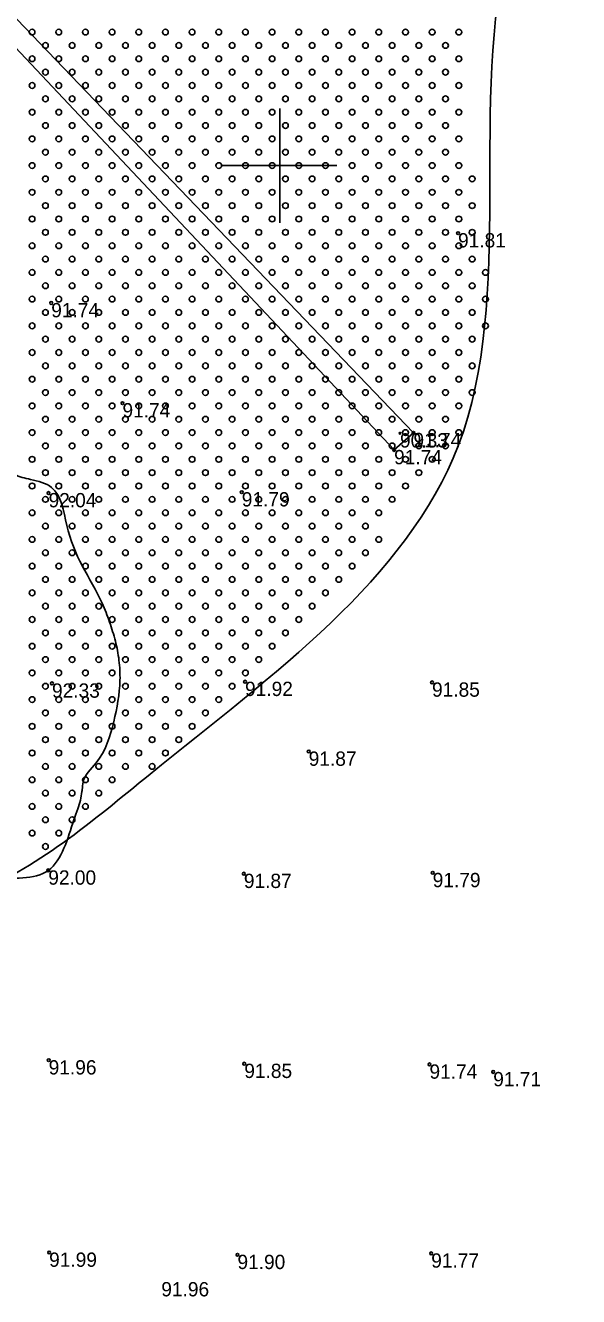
# Model space of a CAD drawing. Extents: x 316000 to 728450, y 314368 to 726000.
# Drawn here: x 725933.2 to 726078.4, y 314703.5 to 315036.8 of the extents above; entities that cross this region are included whole.
import ezdxf

# ---------------------------------------------------------------- set-up
doc = ezdxf.new("R2010")
doc.units = 0
for name, color, linetype in [('GEOD_ELEM_####_####_#', 7, 'Continuous'), ('HIDG_ELEM_####_####_#', 7, 'Continuous'), ('HIDG_GRAV_####_####_#', 7, 'Continuous'), ('RELJ_AATZ_####_TKST_#', 7, 'Continuous'), ('RELJ_ELEM_####_####_#', 7, 'Continuous'), ('RELJ_HORZ_RESN_####_#', 7, 'Continuous'), ('TERT_ELEM_####_####_#', 7, 'Continuous'), ('TERT_KONT_####_####_#', 7, 'Continuous')]:
    doc.layers.add(name, color=color, linetype=linetype)

msp = doc.modelspace()

# ---------------------------------------------------------------- linework, layer by layer
at = {"layer": 'GEOD_ELEM_####_####_#'}
for p, q in [((726000, 315015), (726000, 315000)), ((725985, 315000), (726000, 315000)), ((726000, 315000), (726000, 314985)), ((726000, 315000), (726015, 315000))]:
    msp.add_line(p, q, dxfattribs=at)
at = {"layer": 'HIDG_ELEM_####_####_#'}
msp.add_circle((726031.57, 314929.83), 0.225, dxfattribs=at)
at = {"layer": 'HIDG_GRAV_####_####_#'}
msp.add_lwpolyline([(725550.64, 315437.37), (725654.91, 315324.09), (725793.17, 315176.93), (726030.02, 314925.45), (726035.1, 314929.94), (725796.17, 315178.83)], dxfattribs=at)
at = {"layer": 'RELJ_ELEM_####_####_#'}
for centre in [(726046.8, 314982.3), (725940.03, 314963.98), (725958.73, 314937.73), (726035.1, 314929.94), (726030.02, 314925.45), (725939.33, 314914.16), (725990.03, 314914.39), (725940.23, 314864.25), (725990.9, 314864.69), (726039.97, 314864.51), (726007.6, 314846.4), (725939.26, 314815.23), (725990.59, 314814.36), (726040.15, 314814.58), (725939.36, 314765.47), (725990.7, 314764.55), (726039.3, 314764.36), (726056.03, 314762.38), (725939.48, 314715.05), (725988.91, 314714.46), (726039.76, 314714.83)]:
    msp.add_circle(centre, 0.375, dxfattribs=at)
at = {"layer": 'RELJ_HORZ_RESN_####_#'}
msp.add_spline([(725847.58, 314913.36), (725842.82, 314903.9), (725834.89, 314893.88), (725830, 314887.5), (725824.68, 314882.5), (725823, 314880.5), (725818.46, 314873.33), (725816.42, 314861.94), (725828.62, 314847.89), (725836.39, 314833.94), (725841.85, 314827.21), (725844.92, 314823.94), (725846.54, 314822.33), (725848.21, 314820.75), (725849.87, 314819.28), (725851.54, 314817.96), (725854.93, 314815.69), (725861.88, 314812.56), (725876.18, 314810.77), (725889.21, 314809.58), (725897.6, 314810.61), (725900.35, 314811.35), (725904.45, 314811.73), (725909.6, 314811.98), (725914.71, 314812.55), (725924.78, 314813.21), (725939.26, 314815.23), (725946, 314828.5), (725947.02, 314831.36), (725947.68, 314833.6), (725948.09, 314835.89), (725948.17, 314836.43), (725948.37, 314838.35), (725951.84, 314843.45), (725956.45, 314854.2), (725958.07, 314865.07), (725957.81, 314870.33), (725957.42, 314872.87), (725956.86, 314875.34), (725955.34, 314880.33), (725953.4, 314885.29), (725948.2, 314895.01), (725944.11, 314905.69), (725940.13, 314915.61), (725934.59, 314917.71), (725930.31, 314919.02), (725927.36, 314920.28), (725925.87, 314920.52), (725924.32, 314920.84), (725921.47, 314921.64), (725910.61, 314924.89), (725899.55, 314928.31), (725893.93, 314929.77), (725888.26, 314931.21), (725887.09, 314931.52)], degree=3, dxfattribs=at)
at = {"layer": 'TERT_ELEM_####_####_#'}
for centre in [(725935, 315035), (725942, 315035), (725949, 315035), (725956, 315035), (725963, 315035), (725970, 315035), (725977, 315035), (725984, 315035), (725991, 315035), (725998, 315035), (726005, 315035), (726012, 315035), (726019, 315035), (726026, 315035), (726033, 315035), (726040, 315035), (726047, 315035), (725938.5, 315031.5), (725945.5, 315031.5), (725952.5, 315031.5), (725959.5, 315031.5), (725966.5, 315031.5), (725973.5, 315031.5), (725980.5, 315031.5), (725987.5, 315031.5), (725994.5, 315031.5), (726001.5, 315031.5), (726008.5, 315031.5), (726015.5, 315031.5), (726022.5, 315031.5), (726029.5, 315031.5), (726036.5, 315031.5), (726043.5, 315031.5), (725935, 315028), (725942, 315028), (725949, 315028), (725956, 315028), (725963, 315028), (725970, 315028), (725977, 315028), (725984, 315028), (725991, 315028), (725998, 315028), (726005, 315028), (726012, 315028), (726019, 315028), (726026, 315028), (726033, 315028), (726040, 315028), (726047, 315028), (725938.5, 315024.5), (725945.5, 315024.5), (725952.5, 315024.5), (725959.5, 315024.5), (725966.5, 315024.5), (725973.5, 315024.5), (725980.5, 315024.5), (725987.5, 315024.5), (725994.5, 315024.5), (726001.5, 315024.5), (726008.5, 315024.5), (726015.5, 315024.5), (726022.5, 315024.5), (726029.5, 315024.5), (726036.5, 315024.5), (726043.5, 315024.5), (725935, 315021), (725942, 315021), (725949, 315021), (725956, 315021), (725963, 315021), (725970, 315021), (725977, 315021), (725984, 315021), (725991, 315021), (725998, 315021), (726005, 315021), (726012, 315021), (726019, 315021), (726026, 315021), (726033, 315021), (726040, 315021), (726047, 315021), (725938.5, 315017.5), (725945.5, 315017.5), (725952.5, 315017.5), (725959.5, 315017.5), (725966.5, 315017.5), (725973.5, 315017.5), (725980.5, 315017.5), (725987.5, 315017.5), (725994.5, 315017.5), (726001.5, 315017.5), (726008.5, 315017.5), (726015.5, 315017.5), (726022.5, 315017.5), (726029.5, 315017.5), (726036.5, 315017.5), (726043.5, 315017.5), (725935, 315014), (725942, 315014), (725949, 315014), (725956, 315014), (725963, 315014), (725970, 315014), (725977, 315014), (725984, 315014), (725991, 315014), (725998, 315014), (726005, 315014), (726012, 315014), (726019, 315014), (726026, 315014), (726033, 315014), (726040, 315014), (726047, 315014), (725938.5, 315010.5), (725945.5, 315010.5), (725952.5, 315010.5), (725959.5, 315010.5), (725966.5, 315010.5), (725973.5, 315010.5), (725980.5, 315010.5), (725987.5, 315010.5), (725994.5, 315010.5), (726001.5, 315010.5), (726008.5, 315010.5), (726015.5, 315010.5), (726022.5, 315010.5), (726029.5, 315010.5), (726036.5, 315010.5), (726043.5, 315010.5), (725935, 315007), (725942, 315007), (725949, 315007), (725956, 315007), (725963, 315007), (725970, 315007), (725977, 315007), (725984, 315007), (725991, 315007), (725998, 315007), (726005, 315007), (726012, 315007), (726019, 315007), (726026, 315007), (726033, 315007), (726040, 315007), (726047, 315007), (725938.5, 315003.5), (725945.5, 315003.5), (725952.5, 315003.5), (725959.5, 315003.5), (725966.5, 315003.5), (725973.5, 315003.5), (725980.5, 315003.5), (725987.5, 315003.5), (725994.5, 315003.5), (726001.5, 315003.5), (726008.5, 315003.5), (726015.5, 315003.5), (726022.5, 315003.5), (726029.5, 315003.5), (726036.5, 315003.5), (726043.5, 315003.5), (725935, 315000), (725942, 315000), (725949, 315000), (725956, 315000), (725963, 315000), (725970, 315000), (725977, 315000), (725984, 315000), (725991, 315000), (725998, 315000), (726005, 315000), (726012, 315000), (726019, 315000), (726026, 315000), (726033, 315000), (726040, 315000), (726047, 315000), (725938.5, 314996.5), (725945.5, 314996.5), (725952.5, 314996.5), (725959.5, 314996.5), (725966.5, 314996.5), (725973.5, 314996.5), (725980.5, 314996.5), (725987.5, 314996.5), (725994.5, 314996.5), (726001.5, 314996.5), (726008.5, 314996.5), (726015.5, 314996.5), (726022.5, 314996.5), (726029.5, 314996.5), (726036.5, 314996.5), (726043.5, 314996.5), (726050.5, 314996.5), (725935, 314993), (725942, 314993), (725949, 314993), (725956, 314993), (725963, 314993), (725970, 314993), (725977, 314993), (725984, 314993), (725991, 314993), (725998, 314993), (726005, 314993), (726012, 314993), (726019, 314993), (726026, 314993), (726033, 314993), (726040, 314993), (726047, 314993), (725938.5, 314989.5), (725945.5, 314989.5), (725952.5, 314989.5), (725959.5, 314989.5), (725966.5, 314989.5), (725973.5, 314989.5), (725980.5, 314989.5), (725987.5, 314989.5), (725994.5, 314989.5), (726001.5, 314989.5), (726008.5, 314989.5), (726015.5, 314989.5), (726022.5, 314989.5), (726029.5, 314989.5), (726036.5, 314989.5), (726043.5, 314989.5), (726050.5, 314989.5), (725935, 314986), (725942, 314986), (725949, 314986), (725956, 314986), (725963, 314986), (725970, 314986), (725977, 314986), (725984, 314986), (725991, 314986), (725998, 314986), (726005, 314986), (726012, 314986), (726019, 314986), (726026, 314986), (726033, 314986), (726040, 314986), (726047, 314986), (725938.5, 314982.5), (725945.5, 314982.5), (725952.5, 314982.5), (725959.5, 314982.5), (725966.5, 314982.5), (725973.5, 314982.5), (725980.5, 314982.5), (725987.5, 314982.5), (725994.5, 314982.5), (726001.5, 314982.5), (726008.5, 314982.5), (726015.5, 314982.5), (726022.5, 314982.5), (726029.5, 314982.5), (726036.5, 314982.5), (726043.5, 314982.5), (726050.5, 314982.5), (725935, 314979), (725942, 314979), (725949, 314979), (725956, 314979), (725963, 314979), (725970, 314979), (725977, 314979), (725984, 314979), (725991, 314979), (725998, 314979), (726005, 314979), (726012, 314979), (726019, 314979), (726026, 314979), (726033, 314979), (726040, 314979), (726047, 314979), (725938.5, 314975.5), (725945.5, 314975.5), (725952.5, 314975.5), (725959.5, 314975.5), (725966.5, 314975.5), (725973.5, 314975.5), (725980.5, 314975.5), (725987.5, 314975.5), (725994.5, 314975.5), (726001.5, 314975.5), (726008.5, 314975.5), (726015.5, 314975.5), (726022.5, 314975.5), (726029.5, 314975.5), (726036.5, 314975.5), (726043.5, 314975.5), (726050.5, 314975.5), (725935, 314972), (725942, 314972), (725949, 314972), (725956, 314972), (725963, 314972), (725970, 314972), (725977, 314972), (725984, 314972), (725991, 314972), (725998, 314972), (726005, 314972), (726012, 314972), (726019, 314972), (726026, 314972), (726033, 314972), (726040, 314972), (726047, 314972), (726054, 314972), (725938.5, 314968.5), (725945.5, 314968.5), (725952.5, 314968.5), (725959.5, 314968.5), (725966.5, 314968.5), (725973.5, 314968.5), (725980.5, 314968.5), (725987.5, 314968.5), (725994.5, 314968.5), (726001.5, 314968.5), (726008.5, 314968.5), (726015.5, 314968.5), (726022.5, 314968.5), (726029.5, 314968.5), (726036.5, 314968.5), (726043.5, 314968.5), (726050.5, 314968.5), (725935, 314965), (725942, 314965), (725949, 314965), (725956, 314965), (725963, 314965), (725970, 314965), (725977, 314965), (725984, 314965), (725991, 314965), (725998, 314965), (726005, 314965), (726012, 314965), (726019, 314965), (726026, 314965), (726033, 314965), (726040, 314965), (726047, 314965), (726054, 314965), (725938.5, 314961.5), (725945.5, 314961.5), (725952.5, 314961.5), (725959.5, 314961.5), (725966.5, 314961.5), (725973.5, 314961.5), (725980.5, 314961.5), (725987.5, 314961.5), (725994.5, 314961.5), (726001.5, 314961.5), (726008.5, 314961.5), (726015.5, 314961.5), (726022.5, 314961.5), (726029.5, 314961.5), (726036.5, 314961.5), (726043.5, 314961.5), (726050.5, 314961.5), (725935, 314958), (725942, 314958), (725949, 314958), (725956, 314958), (725963, 314958), (725970, 314958), (725977, 314958), (725984, 314958), (725991, 314958), (725998, 314958), (726005, 314958), (726012, 314958), (726019, 314958), (726026, 314958), (726033, 314958), (726040, 314958), (726047, 314958), (726054, 314958), (725938.5, 314954.5), (725945.5, 314954.5), (725952.5, 314954.5), (725959.5, 314954.5), (725966.5, 314954.5), (725973.5, 314954.5), (725980.5, 314954.5), (725987.5, 314954.5), (725994.5, 314954.5), (726001.5, 314954.5), (726008.5, 314954.5), (726015.5, 314954.5), (726022.5, 314954.5), (726029.5, 314954.5), (726036.5, 314954.5), (726043.5, 314954.5), (726050.5, 314954.5), (725935, 314951), (725942, 314951), (725949, 314951), (725956, 314951), (725963, 314951), (725970, 314951), (725977, 314951), (725984, 314951), (725991, 314951), (725998, 314951), (726005, 314951), (726012, 314951), (726019, 314951), (726026, 314951), (726033, 314951), (726040, 314951), (726047, 314951), (725938.5, 314947.5), (725945.5, 314947.5), (725952.5, 314947.5), (725959.5, 314947.5), (725966.5, 314947.5), (725973.5, 314947.5), (725980.5, 314947.5), (725987.5, 314947.5), (725994.5, 314947.5), (726001.5, 314947.5), (726008.5, 314947.5), (726015.5, 314947.5), (726022.5, 314947.5), (726029.5, 314947.5), (726036.5, 314947.5), (726043.5, 314947.5), (726050.5, 314947.5), (725935, 314944), (725942, 314944), (725949, 314944), (725956, 314944), (725963, 314944), (725970, 314944), (725977, 314944), (725984, 314944), (725991, 314944), (725998, 314944), (726005, 314944), (726012, 314944), (726019, 314944), (726026, 314944), (726033, 314944), (726040, 314944), (726047, 314944), (725938.5, 314940.5), (725945.5, 314940.5), (725952.5, 314940.5), (725959.5, 314940.5), (725966.5, 314940.5), (725973.5, 314940.5), (725980.5, 314940.5), (725987.5, 314940.5), (725994.5, 314940.5), (726001.5, 314940.5), (726008.5, 314940.5), (726015.5, 314940.5), (726022.5, 314940.5), (726029.5, 314940.5), (726036.5, 314940.5), (726043.5, 314940.5), (726050.5, 314940.5), (725935, 314937), (725942, 314937), (725949, 314937), (725956, 314937), (725963, 314937), (725970, 314937), (725977, 314937), (725984, 314937), (725991, 314937), (725998, 314937), (726005, 314937), (726012, 314937), (726019, 314937), (726026, 314937), (726033, 314937), (726040, 314937), (726047, 314937), (725938.5, 314933.5), (725945.5, 314933.5), (725952.5, 314933.5), (725959.5, 314933.5), (725966.5, 314933.5), (725973.5, 314933.5), (725980.5, 314933.5), (725987.5, 314933.5), (725994.5, 314933.5), (726001.5, 314933.5), (726008.5, 314933.5), (726015.5, 314933.5), (726022.5, 314933.5), (726029.5, 314933.5), (726036.5, 314933.5), (726043.5, 314933.5), (725935, 314930), (725942, 314930), (725949, 314930), (725956, 314930), (725963, 314930), (725970, 314930), (725977, 314930), (725984, 314930), (725991, 314930), (725998, 314930), (726005, 314930), (726012, 314930), (726019, 314930), (726026, 314930), (726033, 314930), (726040, 314930), (726047, 314930), (725938.5, 314926.5), (725945.5, 314926.5), (725952.5, 314926.5), (725959.5, 314926.5), (725966.5, 314926.5), (725973.5, 314926.5), (725980.5, 314926.5), (725987.5, 314926.5), (725994.5, 314926.5), (726001.5, 314926.5), (726008.5, 314926.5), (726015.5, 314926.5), (726022.5, 314926.5), (726029.5, 314926.5), (726036.5, 314926.5), (726043.5, 314926.5), (725935, 314923), (725942, 314923), (725949, 314923), (725956, 314923), (725963, 314923), (725970, 314923), (725977, 314923), (725984, 314923), (725991, 314923), (725998, 314923), (726005, 314923), (726012, 314923), (726019, 314923), (726026, 314923), (726033, 314923), (726040, 314923), (725938.5, 314919.5), (725945.5, 314919.5), (725952.5, 314919.5), (725959.5, 314919.5), (725966.5, 314919.5), (725973.5, 314919.5), (725980.5, 314919.5), (725987.5, 314919.5), (725994.5, 314919.5), (726001.5, 314919.5), (726008.5, 314919.5), (726015.5, 314919.5), (726022.5, 314919.5), (726029.5, 314919.5), (726036.5, 314919.5), (725935, 314916), (725942, 314916), (725949, 314916), (725956, 314916), (725963, 314916), (725970, 314916), (725977, 314916), (725984, 314916), (725991, 314916), (725998, 314916), (726005, 314916), (726012, 314916), (726019, 314916), (726026, 314916), (726033, 314916), (725938.5, 314912.5), (725945.5, 314912.5), (725952.5, 314912.5), (725959.5, 314912.5), (725966.5, 314912.5), (725973.5, 314912.5), (725980.5, 314912.5), (725987.5, 314912.5), (725994.5, 314912.5), (726001.5, 314912.5), (726008.5, 314912.5), (726015.5, 314912.5), (726022.5, 314912.5), (726029.5, 314912.5), (725935, 314909), (725942, 314909), (725949, 314909), (725956, 314909), (725963, 314909), (725970, 314909), (725977, 314909), (725984, 314909), (725991, 314909), (725998, 314909), (726005, 314909), (726012, 314909), (726019, 314909), (726026, 314909), (725938.5, 314905.5), (725945.5, 314905.5), (725952.5, 314905.5), (725959.5, 314905.5), (725966.5, 314905.5), (725973.5, 314905.5), (725980.5, 314905.5), (725987.5, 314905.5), (725994.5, 314905.5), (726001.5, 314905.5), (726008.5, 314905.5), (726015.5, 314905.5), (726022.5, 314905.5), (725935, 314902), (725942, 314902), (725949, 314902), (725956, 314902), (725963, 314902), (725970, 314902), (725977, 314902), (725984, 314902), (725991, 314902), (725998, 314902), (726005, 314902), (726012, 314902), (726019, 314902), (726026, 314902), (725938.5, 314898.5), (725945.5, 314898.5), (725952.5, 314898.5), (725959.5, 314898.5), (725966.5, 314898.5), (725973.5, 314898.5), (725980.5, 314898.5), (725987.5, 314898.5), (725994.5, 314898.5), (726001.5, 314898.5), (726008.5, 314898.5), (726015.5, 314898.5), (726022.5, 314898.5), (725935, 314895), (725942, 314895), (725949, 314895), (725956, 314895), (725963, 314895), (725970, 314895), (725977, 314895), (725984, 314895), (725991, 314895), (725998, 314895), (726005, 314895), (726012, 314895), (726019, 314895), (725938.5, 314891.5), (725945.5, 314891.5), (725952.5, 314891.5), (725959.5, 314891.5), (725966.5, 314891.5), (725973.5, 314891.5), (725980.5, 314891.5), (725987.5, 314891.5), (725994.5, 314891.5), (726001.5, 314891.5), (726008.5, 314891.5), (726015.5, 314891.5), (725935, 314888), (725942, 314888), (725949, 314888), (725956, 314888), (725963, 314888), (725970, 314888), (725977, 314888), (725984, 314888), (725991, 314888), (725998, 314888), (726005, 314888), (726012, 314888), (725938.5, 314884.5), (725945.5, 314884.5), (725952.5, 314884.5), (725959.5, 314884.5), (725966.5, 314884.5), (725973.5, 314884.5), (725980.5, 314884.5), (725987.5, 314884.5), (725994.5, 314884.5), (726001.5, 314884.5), (726008.5, 314884.5), (725935, 314881), (725942, 314881), (725949, 314881), (725956, 314881), (725963, 314881), (725970, 314881), (725977, 314881), (725984, 314881), (725991, 314881), (725998, 314881), (726005, 314881), (725938.5, 314877.5), (725945.5, 314877.5), (725952.5, 314877.5), (725959.5, 314877.5), (725966.5, 314877.5), (725973.5, 314877.5), (725980.5, 314877.5), (725987.5, 314877.5), (725994.5, 314877.5), (726001.5, 314877.5), (725935, 314874), (725942, 314874), (725949, 314874), (725956, 314874), (725963, 314874), (725970, 314874), (725977, 314874), (725984, 314874), (725991, 314874), (725998, 314874), (725938.5, 314870.5), (725945.5, 314870.5), (725952.5, 314870.5), (725959.5, 314870.5), (725966.5, 314870.5), (725973.5, 314870.5), (725980.5, 314870.5), (725987.5, 314870.5), (725994.5, 314870.5), (725935, 314867), (725942, 314867), (725949, 314867), (725956, 314867), (725963, 314867), (725970, 314867), (725977, 314867), (725984, 314867), (725991, 314867), (725938.5, 314863.5), (725945.5, 314863.5), (725952.5, 314863.5), (725959.5, 314863.5), (725966.5, 314863.5), (725973.5, 314863.5), (725980.5, 314863.5), (725987.5, 314863.5), (725935, 314860), (725942, 314860), (725949, 314860), (725956, 314860), (725963, 314860), (725970, 314860), (725977, 314860), (725984, 314860), (725938.5, 314856.5), (725945.5, 314856.5), (725952.5, 314856.5), (725959.5, 314856.5), (725966.5, 314856.5), (725973.5, 314856.5), (725980.5, 314856.5), (725935, 314853), (725942, 314853), (725949, 314853), (725956, 314853), (725963, 314853), (725970, 314853), (725977, 314853), (725938.5, 314849.5), (725945.5, 314849.5), (725952.5, 314849.5), (725959.5, 314849.5), (725966.5, 314849.5), (725973.5, 314849.5), (725935, 314846), (725942, 314846), (725949, 314846), (725956, 314846), (725963, 314846), (725970, 314846), (725938.5, 314842.5), (725945.5, 314842.5), (725952.5, 314842.5), (725959.5, 314842.5), (725966.5, 314842.5), (725935, 314839), (725942, 314839), (725949, 314839), (725956, 314839), (725938.5, 314835.5), (725945.5, 314835.5), (725952.5, 314835.5), (725935, 314832), (725942, 314832), (725949, 314832), (725938.5, 314828.5), (725945.5, 314828.5), (725935, 314825), (725942, 314825), (725938.5, 314821.5)]:
    msp.add_circle(centre, 0.75, dxfattribs=at)
at = {"layer": 'TERT_KONT_####_####_#'}
msp.add_spline([(726171.05, 315177.78), (726060.22, 315058.34), (726046.85, 314926.57), (725966, 314840.49), (725918.95, 314808.85), (725841.04, 314808.85), (725695.46, 314898.17)], degree=3, dxfattribs=at)

# ---------------------------------------------------------------- texts
at = {"layer": 'RELJ_AATZ_####_TKST_#'}
for s, p in [('91.81', (726046.8, 314978.55)), ('91.74', (725940.03, 314960.23)), ('91.74', (725958.73, 314933.98)), ('90.33', (726031.57, 314926.08)), ('91.74', (726035.1, 314926.18)), ('91.74', (726030.02, 314921.7)), ('92.04', (725939.33, 314910.41)), ('91.79', (725990.03, 314910.64)), ('92.33', (725940.23, 314860.5)), ('91.92', (725990.9, 314860.94)), ('91.85', (726039.97, 314860.76)), ('91.87', (726007.6, 314842.65)), ('92.00', (725939.26, 314811.48)), ('91.87', (725990.59, 314810.61)), ('91.79', (726040.15, 314810.83)), ('91.96', (725939.36, 314761.72)), ('91.85', (725990.7, 314760.8)), ('91.74', (726039.3, 314760.61)), ('91.71', (726056.03, 314758.63)), ('91.99', (725939.48, 314711.3)), ('91.90', (725988.91, 314710.71)), ('91.77', (726039.76, 314711.08)), ('91.96', (725968.92, 314703.55))]:
    msp.add_text(s, height=3.75, dxfattribs=at).set_placement(p)

doc.saveas('drawing.dxf')
